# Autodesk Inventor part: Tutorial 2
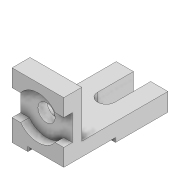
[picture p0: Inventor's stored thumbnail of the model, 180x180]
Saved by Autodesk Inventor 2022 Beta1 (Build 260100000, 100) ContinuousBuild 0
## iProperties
Created: 2021-03
Part Number: Tutorial 2
Material: Generic
Document SubType Name: Modeling
Designer: ASUS Laptop
Density: 1 g/cm^3
Appearance: Default
Author: ASUS Laptop
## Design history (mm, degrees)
sketch "Sketch1"
  geometry: L1 (0, 0)-(90, 0); L2 (90, 0)-(90, -25); L3 (90, -25)-(25, -25); L4 (25, -25)-(25, -145); L5 (25, -145)-(0, -145); L6 (0, -145)-(0, 0)
  constraints: 12 end point, 6 perpendicular, 1 horizontal
  dimensions: "d0" = 145 distance of L5.end L1.start; "d1" = 90 distance between parallel lines of L2 L6; "d2" = 25 distance of L1.end L2.end
extrude "Extrusion1" new body sketch "Sketch1" stored distance "d4" = 72; taper "d5" = 0 deg
sketch "Sketch2"
  geometry: L1 (0, 0)-(72, 0); L2 (72, 0)-(72, 6); L3 (72, 6)-(0, 6); L4 (0, 6)-(0, 0)
  constraints: 8 end point, 2 parallel, 1 horizontal, 1 perpendicular
  dimensions: "d6" = 72 distance of L1.start L1.end; "d7" = 6 distance between parallel lines of L1 L3
extrude "Extrusion2" cut sketch "Sketch2" distance "d8" = 50; taper "d9" = 0 deg
sketch "Sketch3"
  geometry: L1 (12, -24)-(0, -24); L2 (0, -90)-(0, 0) reference; L3 (0, -24)-(0, -60); L4 (0, -60)-(12, -60); L5 (60, -24)-(72, -24); L6 (72, 0)-(72, -84) reference; L7 (72, -24)-(72, -60); L8 (72, -60)-(60, -60); L9 (72, -90)-(22, -90) reference; L10 (0, -90)-(22, -90) reference; A1 r 30 centre (36, -42) between (12, -60) and (60, -60); A2 r 30 centre (36, -42) between (60, -24) and (12, -24); 3 further points
  constraints: 12 end point, 4 point on circle, 4 point on line, 2 centre point, 2 perpendicular, 1 collinear, 1 concentric, 1 horizontal, 1 parallel, 1 vertical
  dimensions: "d10" = 30 radius of A2; "d11" = 36 distance from line of A1.centre L2; "d12" = 48 distance from line of L9 A1.centre; "d13" = 30 distance between parallel lines of L4 L10; "d14" = 36 distance between parallel lines of L4 L1
extrude "Extrusion3" cut sketch "Sketch3" distance "d15" = 12; taper "d16" = 0 deg
sketch "Sketch4"
  geometry: C1 r 12 at (36, -42); A1 r 30 centre (36, -42) between (60, -24) and (12, -24) reference; 1 further point
  constraints: 1 centre point, 1 concentric
  dimensions: "d17" = 24 diameter of C1
extrude "Extrusion4" cut sketch "Sketch4" extent not by distance; stored distance "d18" = 10; taper "d19" = 0 deg
sketch "Sketch5"
  geometry: L1 (24, 120)-(24, 70); L2 (48, 70)-(48, 120); L3 (48, 120)-(24, 120); L4 (72, 120)-(72, 0) reference; A1 r 12 centre (36, 70) between (24, 70) and (48, 70); 2 further points
  constraints: 6 end point, 2 point on circle, 2 tangent, 1 centre point, 1 parallel, 1 perpendicular, 1 point on line, 1 vertical
  dimensions: "d20" = 36 distance from line of A1.centre L4; "d21" = 12 radius of A1; "d22" = 50 distance of L2.start L2.end
extrude "Extrusion5" cut sketch "Sketch5" extent not by distance; stored distance "d23" = 0; taper "d24" = 0 deg
body "Solid1"
